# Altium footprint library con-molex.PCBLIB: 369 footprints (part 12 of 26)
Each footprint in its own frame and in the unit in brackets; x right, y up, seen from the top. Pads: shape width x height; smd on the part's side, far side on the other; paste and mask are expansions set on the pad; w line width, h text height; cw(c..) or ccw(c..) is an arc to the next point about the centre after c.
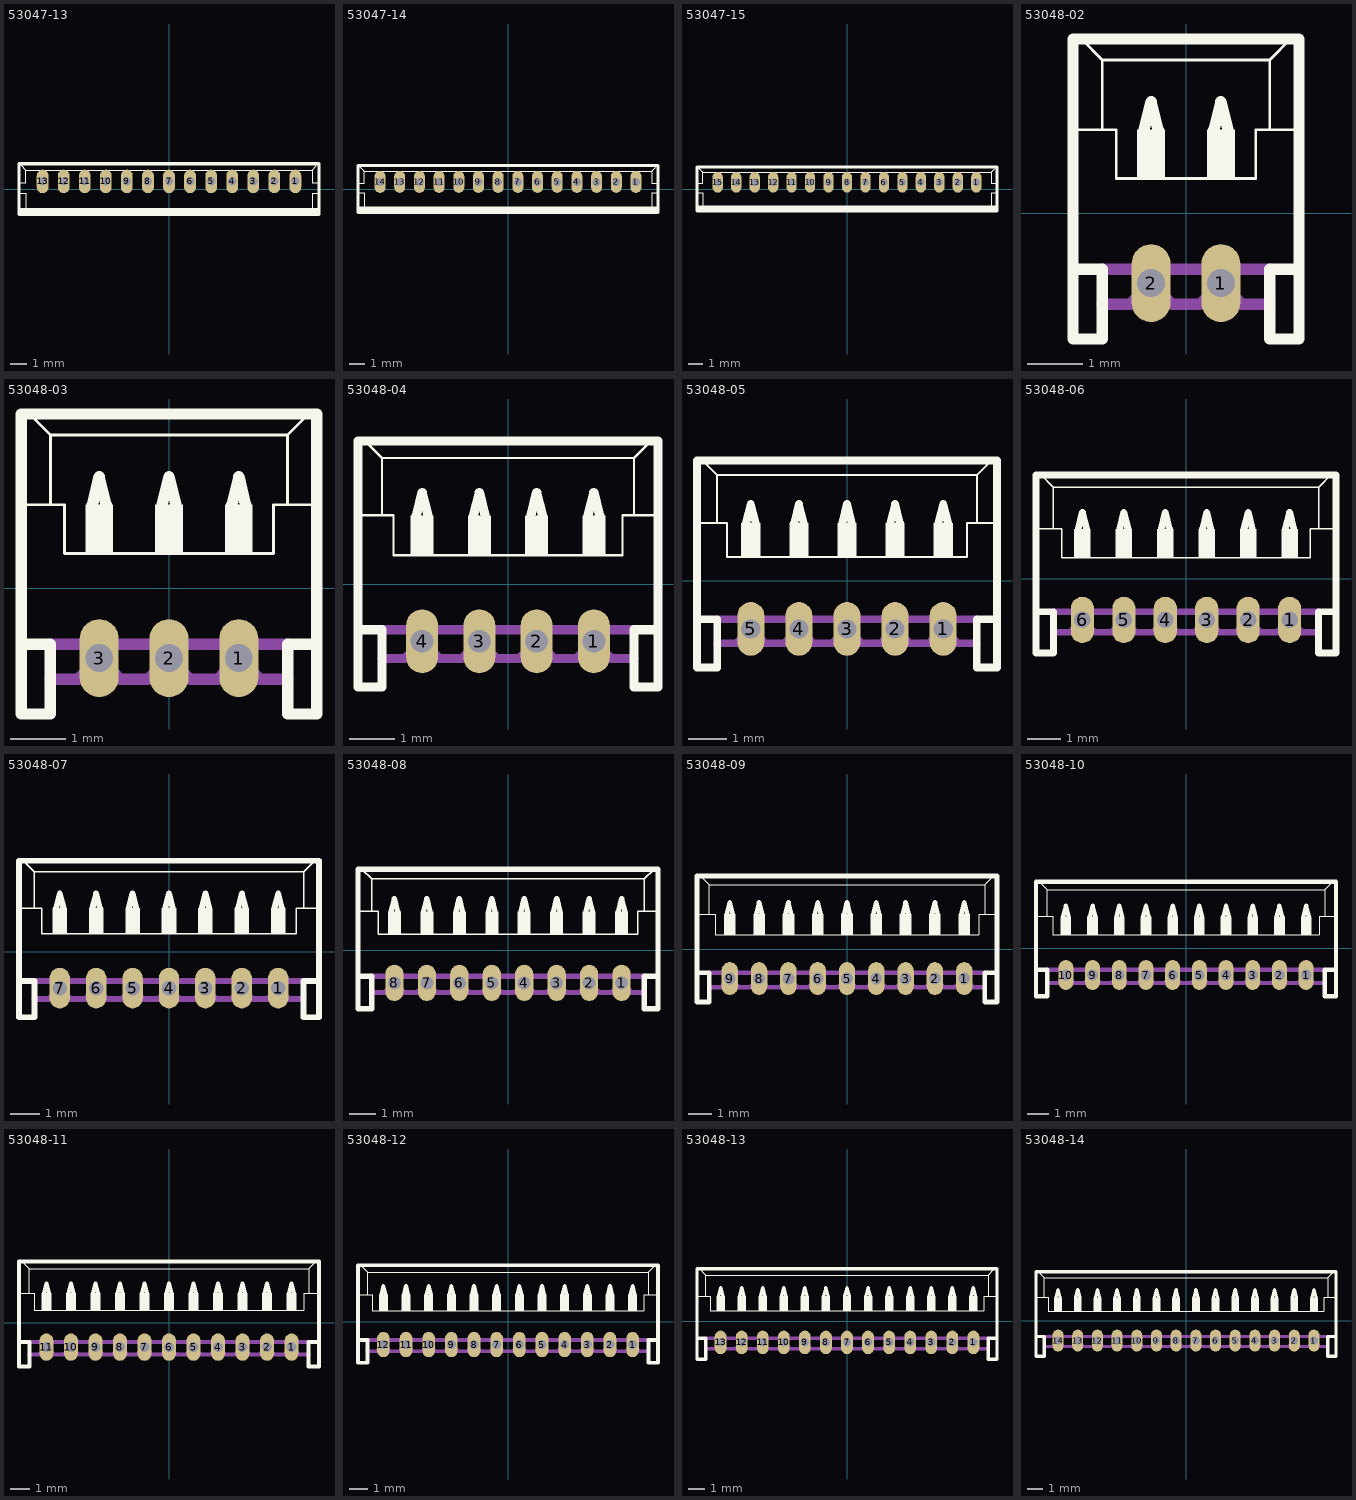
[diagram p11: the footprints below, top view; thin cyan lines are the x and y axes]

## 53047-13 [mil]
pads (13):
  oval 27.5x55 hole 19.69: 1(295.28,17.72) 2(246.06,17.72) 3(196.85,17.72) 4(147.64,17.72) 5(98.43,17.72) 6(49.21,17.72) 7(0,17.72) 8(-49.21,17.72) 9(-98.43,17.72) 10(-147.64,17.72) 11(-196.85,17.72) 12(-246.06,17.72) 13(-295.28,17.72)
Top Overlay:
  rectangle: -349.41,-59.06 349.41,-44.29
  lines w2: -349.41,-9.84 -334.65,-9.84 -334.65,-49.21 ; -349.41,14.76 -334.65,14.76 -334.65,44.29 ; -344.49,54.13 -334.65,44.29 ; 334.65,-49.21 334.65,-9.84 349.41,-9.84 ; 344.49,54.13 334.65,44.29 ; 349.41,14.76 334.65,14.76 334.65,44.29 ; -334.65,44.29 334.65,44.29
  lines w8: -350.39,-59.06 350.39,-59.06 350.39,59.06 -350.39,59.06 -350.39,-59.06

## 53047-14 [mil]
pads (14):
  oval 27.5x55 hole 19.69: 1(319.88,17.72) 2(270.67,17.72) 3(221.46,17.72) 4(172.24,17.72) 5(123.03,17.72) 6(73.82,17.72) 7(24.61,17.72) 8(-24.61,17.72) 9(-73.82,17.72) 10(-123.03,17.72) 11(-172.24,17.72) 12(-221.46,17.72) 13(-270.67,17.72) 14(-319.88,17.72)
Top Overlay:
  rectangle: -374.02,-59.06 374.02,-44.29
  lines w2: -374.02,-9.84 -359.25,-9.84 -359.25,-49.21 ; -374.02,14.76 -359.25,14.76 -359.25,44.29 ; -369.09,54.13 -359.25,44.29 ; 359.25,-49.21 359.25,-9.84 374.02,-9.84 ; 369.09,54.13 359.25,44.29 ; 374.02,14.76 359.25,14.76 359.25,44.29 ; -359.25,44.29 359.25,44.29
  lines w8: -375,-59.06 375,-59.06 375,59.06 -375,59.06 -375,-59.06

## 53047-15 [mil]
pads (15):
  oval 27.5x55 hole 19.69: 1(344.49,17.72) 2(295.28,17.72) 3(246.06,17.72) 4(196.85,17.72) 5(147.64,17.72) 6(98.43,17.72) 7(49.21,17.72) 8(0,17.72) 9(-49.21,17.72) 10(-98.43,17.72) 11(-147.64,17.72) 12(-196.85,17.72) 13(-246.06,17.72) 14(-295.28,17.72) 15(-344.49,17.72)
Top Overlay:
  rectangle: -398.62,-59.06 398.62,-44.29
  lines w2: -398.62,-9.84 -383.86,-9.84 -383.86,-49.21 ; -398.62,14.76 -383.86,14.76 -383.86,44.29 ; -393.7,54.13 -383.86,44.29 ; 383.86,-49.21 383.86,-9.84 398.62,-9.84 ; 393.7,54.13 383.86,44.29 ; 398.62,14.76 383.86,14.76 383.86,44.29 ; -383.86,44.29 383.86,44.29
  lines w8: -399.61,-59.06 399.61,-59.06 399.61,59.06 -399.61,59.06 -399.61,-59.06

## 53048-02 [mil]
pads (2):
  oval 27.5x55 hole 19.69: 1(24.61,-49.21) 2(-24.61,-49.21)
Top Overlay:
  rectangle: -34.45,24.61 -14.76,59.06
  rectangle: 14.76,24.61 34.45,59.06
  lines w2: -78.74,59.06 -59.06,59.06 ; -73.82,123.03 -59.06,108.27 ; 73.82,123.03 59.06,108.27 ; 78.74,59.06 59.06,59.06 ; -59.06,59.06 -49.21,59.06 -49.21,24.61 49.21,24.61 49.21,59.06 59.06,59.06 ; -59.06,59.06 -59.06,108.27 ; -59.06,108.27 59.06,108.27 ; 59.06,59.06 59.06,108.27
  lines w8: -78.74,-39.37 -59.06,-39.37 -59.06,-88.58 -79.72,-88.58 -79.72,123.03 -73.82,123.03 73.82,123.03 79.72,123.03 79.72,-88.58 59.06,-88.58 59.06,-39.37 78.74,-39.37 ; -29.53,59.06 -24.61,78.74 -19.69,59.06 ; 19.69,59.06 24.61,78.74 29.53,59.06
Mechanical 16:
  rectangle: -34.45,-59.06 -14.76,-39.37
  rectangle: 14.76,-59.06 34.45,-39.37
  lines w8: -59.06,-63.98 -39.37,-63.98 -34.45,-59.06 ; -59.06,-39.37 59.06,-39.37 ; -14.76,-59.06 -9.84,-63.98 9.84,-63.98 14.76,-59.06 ; 34.45,-59.06 39.37,-63.98 59.06,-63.98

## 53048-03 [mil]
pads (3):
  oval 27.5x55 hole 19.69: 1(49.21,-49.21) 2(0,-49.21) 3(-49.21,-49.21)
Top Overlay:
  rectangle: -59.06,24.61 -39.37,59.06
  rectangle: -9.84,24.61 9.84,59.06
  rectangle: 39.37,24.61 59.06,59.06
  lines w2: -103.35,59.06 -83.66,59.06 ; -98.43,123.03 -83.66,108.27 ; 98.43,123.03 83.66,108.27 ; 103.35,59.06 83.66,59.06 ; -83.66,59.06 -73.82,59.06 -73.82,24.61 73.82,24.61 73.82,59.06 83.66,59.06 ; -83.66,59.06 -83.66,108.27 ; -83.66,108.27 83.66,108.27 ; 83.66,59.06 83.66,108.27
  lines w8: -103.35,-39.37 -83.66,-39.37 -83.66,-88.58 -104.33,-88.58 -104.33,123.03 -98.43,123.03 98.43,123.03 104.33,123.03 104.33,-88.58 83.66,-88.58 83.66,-39.37 103.35,-39.37 ; -54.13,59.06 -49.21,78.74 -44.29,59.06 ; -4.92,59.06 0,78.74 4.92,59.06 ; 44.29,59.06 49.21,78.74 54.13,59.06
Mechanical 16:
  rectangle: -59.06,-59.06 -39.37,-39.37
  rectangle: -9.84,-59.06 9.84,-39.37
  rectangle: 39.37,-59.06 59.06,-39.37
  lines w8: -83.66,-63.98 -63.98,-63.98 -59.06,-59.06 ; -83.66,-39.37 83.66,-39.37 ; -39.37,-59.06 -34.45,-63.98 -14.76,-63.98 -9.84,-59.06 ; 9.84,-59.06 14.76,-63.98 34.45,-63.98 39.37,-59.06 ; 59.06,-59.06 63.98,-63.98 83.66,-63.98

## 53048-04 [mil]
pads (4):
  oval 27.5x55 hole 19.69: 1(73.82,-49.21) 2(24.61,-49.21) 3(-24.61,-49.21) 4(-73.82,-49.21)
Top Overlay:
  rectangle: -83.66,24.61 -63.98,59.06
  rectangle: -34.45,24.61 -14.76,59.06
  rectangle: 14.76,24.61 34.45,59.06
  rectangle: 63.98,24.61 83.66,59.06
  lines w2: -127.95,59.06 -108.27,59.06 ; -123.03,123.03 -108.27,108.27 ; 123.03,123.03 108.27,108.27 ; 127.95,59.06 108.27,59.06 ; -108.27,59.06 -98.43,59.06 -98.43,24.61 98.43,24.61 98.43,59.06 108.27,59.06 ; -108.27,59.06 -108.27,108.27 ; -108.27,108.27 108.27,108.27 ; 108.27,59.06 108.27,108.27
  lines w8: -127.95,-39.37 -108.27,-39.37 -108.27,-88.58 -128.94,-88.58 -128.94,123.03 -123.03,123.03 123.03,123.03 128.94,123.03 128.94,-88.58 108.27,-88.58 108.27,-39.37 127.95,-39.37 ; -78.74,59.06 -73.82,78.74 -68.9,59.06 ; -29.53,59.06 -24.61,78.74 -19.69,59.06 ; 19.69,59.06 24.61,78.74 29.53,59.06 ; 68.9,59.06 73.82,78.74 78.74,59.06
Mechanical 16:
  rectangle: -83.66,-59.06 -63.98,-39.37
  rectangle: -34.45,-59.06 -14.76,-39.37
  rectangle: 14.76,-59.06 34.45,-39.37
  rectangle: 63.98,-59.06 83.66,-39.37
  lines w8: -108.27,-63.98 -88.58,-63.98 -83.66,-59.06 ; -108.27,-39.37 108.27,-39.37 ; -63.98,-59.06 -59.06,-63.98 -39.37,-63.98 -34.45,-59.06 ; -14.76,-59.06 -9.84,-63.98 9.84,-63.98 14.76,-59.06 ; 34.45,-59.06 39.37,-63.98 59.06,-63.98 63.98,-59.06 ; 83.66,-59.06 88.58,-63.98 108.27,-63.98

## 53048-05 [mil]
pads (5):
  oval 27.5x55 hole 19.69: 1(98.43,-49.21) 2(49.21,-49.21) 3(0,-49.21) 4(-49.21,-49.21) 5(-98.43,-49.21)
Top Overlay:
  rectangle: -108.27,24.61 -88.58,59.06
  rectangle: -59.06,24.61 -39.37,59.06
  rectangle: -9.84,24.61 9.84,59.06
  rectangle: 39.37,24.61 59.06,59.06
  rectangle: 88.58,24.61 108.27,59.06
  lines w2: -152.56,59.06 -132.87,59.06 ; -147.64,123.03 -132.87,108.27 ; 147.64,123.03 132.87,108.27 ; 152.56,59.06 132.87,59.06 ; -132.87,59.06 -123.03,59.06 -123.03,24.61 123.03,24.61 123.03,59.06 132.87,59.06 ; -132.87,59.06 -132.87,108.27 ; -132.87,108.27 132.87,108.27 ; 132.87,59.06 132.87,108.27
  lines w8: -152.56,-39.37 -132.87,-39.37 -132.87,-88.58 -153.54,-88.58 -153.54,123.03 -147.64,123.03 147.64,123.03 153.54,123.03 153.54,-88.58 132.87,-88.58 132.87,-39.37 152.56,-39.37 ; -103.35,59.06 -98.43,78.74 -93.5,59.06 ; -54.13,59.06 -49.21,78.74 -44.29,59.06 ; -4.92,59.06 0,78.74 4.92,59.06 ; 44.29,59.06 49.21,78.74 54.13,59.06 ; 93.5,59.06 98.43,78.74 103.35,59.06
Mechanical 16:
  rectangle: -108.27,-59.06 -88.58,-39.37
  rectangle: -59.06,-59.06 -39.37,-39.37
  rectangle: -9.84,-59.06 9.84,-39.37
  rectangle: 39.37,-59.06 59.06,-39.37
  rectangle: 88.58,-59.06 108.27,-39.37
  lines w8: -132.87,-63.98 -113.19,-63.98 -108.27,-59.06 ; -132.87,-39.37 132.87,-39.37 ; -88.58,-59.06 -83.66,-63.98 -63.98,-63.98 -59.06,-59.06 ; -39.37,-59.06 -34.45,-63.98 -14.76,-63.98 -9.84,-59.06 ; 9.84,-59.06 14.76,-63.98 34.45,-63.98 39.37,-59.06 ; 59.06,-59.06 63.98,-63.98 83.66,-63.98 88.58,-59.06 ; 108.27,-59.06 113.19,-63.98 132.87,-63.98

## 53048-06 [mil]
pads (6):
  oval 27.5x55 hole 19.69: 1(123.03,-49.21) 2(73.82,-49.21) 3(24.61,-49.21) 4(-24.61,-49.21) 5(-73.82,-49.21) 6(-123.03,-49.21)
Top Overlay:
  rectangle: -132.87,24.61 -113.19,59.06
  rectangle: -83.66,24.61 -63.98,59.06
  rectangle: -34.45,24.61 -14.76,59.06
  rectangle: 14.76,24.61 34.45,59.06
  rectangle: 63.98,24.61 83.66,59.06
  rectangle: 113.19,24.61 132.87,59.06
  lines w2: -177.17,59.06 -157.48,59.06 ; -172.24,123.03 -157.48,108.27 ; 172.24,123.03 157.48,108.27 ; 177.17,59.06 157.48,59.06 ; -157.48,59.06 -147.64,59.06 -147.64,24.61 147.64,24.61 147.64,59.06 157.48,59.06 ; -157.48,59.06 -157.48,108.27 ; -157.48,108.27 157.48,108.27 ; 157.48,59.06 157.48,108.27
  lines w8: -177.17,-39.37 -157.48,-39.37 -157.48,-88.58 -178.15,-88.58 -178.15,123.03 -172.24,123.03 172.24,123.03 178.15,123.03 178.15,-88.58 157.48,-88.58 157.48,-39.37 177.17,-39.37 ; -127.95,59.06 -123.03,78.74 -118.11,59.06 ; -78.74,59.06 -73.82,78.74 -68.9,59.06 ; -29.53,59.06 -24.61,78.74 -19.69,59.06 ; 19.69,59.06 24.61,78.74 29.53,59.06 ; 68.9,59.06 73.82,78.74 78.74,59.06 ; 118.11,59.06 123.03,78.74 127.95,59.06
Mechanical 16:
  rectangle: -132.87,-59.06 -113.19,-39.37
  rectangle: -83.66,-59.06 -63.98,-39.37
  rectangle: -34.45,-59.06 -14.76,-39.37
  rectangle: 14.76,-59.06 34.45,-39.37
  rectangle: 63.98,-59.06 83.66,-39.37
  rectangle: 113.19,-59.06 132.87,-39.37
  lines w8: -157.48,-63.98 -137.8,-63.98 -132.87,-59.06 ; -157.48,-39.37 157.48,-39.37 ; -113.19,-59.06 -108.27,-63.98 -88.58,-63.98 -83.66,-59.06 ; -63.98,-59.06 -59.06,-63.98 -39.37,-63.98 -34.45,-59.06 ; -14.76,-59.06 -9.84,-63.98 9.84,-63.98 14.76,-59.06 ; 34.45,-59.06 39.37,-63.98 59.06,-63.98 63.98,-59.06 ; 83.66,-59.06 88.58,-63.98 108.27,-63.98 113.19,-59.06 ; 132.87,-59.06 137.8,-63.98 157.48,-63.98

## 53048-07 [mil]
pads (7):
  oval 27.5x55 hole 19.69: 1(147.64,-49.21) 2(98.43,-49.21) 3(49.21,-49.21) 4(0,-49.21) 5(-49.21,-49.21) 6(-98.43,-49.21) 7(-147.64,-49.21)
Top Overlay:
  rectangle: -157.48,24.61 -137.8,59.06
  rectangle: -108.27,24.61 -88.58,59.06
  rectangle: -59.06,24.61 -39.37,59.06
  rectangle: -9.84,24.61 9.84,59.06
  rectangle: 39.37,24.61 59.06,59.06
  rectangle: 88.58,24.61 108.27,59.06
  rectangle: 137.8,24.61 157.48,59.06
  lines w2: -201.77,59.06 -182.09,59.06 ; -196.85,123.03 -182.09,108.27 ; 196.85,123.03 182.09,108.27 ; 201.77,59.06 182.09,59.06 ; -182.09,59.06 -172.24,59.06 -172.24,24.61 172.24,24.61 172.24,59.06 182.09,59.06 ; -182.09,59.06 -182.09,108.27 ; -182.09,108.27 182.09,108.27 ; 182.09,59.06 182.09,108.27
  lines w8: -201.77,-39.37 -182.09,-39.37 -182.09,-88.58 -202.76,-88.58 -202.76,123.03 -196.85,123.03 196.85,123.03 202.76,123.03 202.76,-88.58 182.09,-88.58 182.09,-39.37 201.77,-39.37 ; -152.56,59.06 -147.64,78.74 -142.72,59.06 ; -103.35,59.06 -98.43,78.74 -93.5,59.06 ; -54.13,59.06 -49.21,78.74 -44.29,59.06 ; -4.92,59.06 0,78.74 4.92,59.06 ; 44.29,59.06 49.21,78.74 54.13,59.06 ; 93.5,59.06 98.43,78.74 103.35,59.06 ; 142.72,59.06 147.64,78.74 152.56,59.06
Mechanical 16:
  rectangle: -157.48,-59.06 -137.8,-39.37
  rectangle: -108.27,-59.06 -88.58,-39.37
  rectangle: -59.06,-59.06 -39.37,-39.37
  rectangle: -9.84,-59.06 9.84,-39.37
  rectangle: 39.37,-59.06 59.06,-39.37
  rectangle: 88.58,-59.06 108.27,-39.37
  rectangle: 137.8,-59.06 157.48,-39.37
  lines w8: -182.09,-63.98 -162.4,-63.98 -157.48,-59.06 ; -182.09,-39.37 182.09,-39.37 ; -137.8,-59.06 -132.87,-63.98 -113.19,-63.98 -108.27,-59.06 ; -88.58,-59.06 -83.66,-63.98 -63.98,-63.98 -59.06,-59.06 ; -39.37,-59.06 -34.45,-63.98 -14.76,-63.98 -9.84,-59.06 ; 9.84,-59.06 14.76,-63.98 34.45,-63.98 39.37,-59.06 ; 59.06,-59.06 63.98,-63.98 83.66,-63.98 88.58,-59.06 ; 108.27,-59.06 113.19,-63.98 132.87,-63.98 137.8,-59.06 ; 157.48,-59.06 162.4,-63.98 182.09,-63.98

## 53048-08 [mil]
pads (8):
  oval 27.5x55 hole 19.69: 1(172.24,-49.21) 2(123.03,-49.21) 3(73.82,-49.21) 4(24.61,-49.21) 5(-24.61,-49.21) 6(-73.82,-49.21) 7(-123.03,-49.21) 8(-172.24,-49.21)
Top Overlay:
  rectangle: -182.09,24.61 -162.4,59.06
  rectangle: -132.87,24.61 -113.19,59.06
  rectangle: -83.66,24.61 -63.98,59.06
  rectangle: -34.45,24.61 -14.76,59.06
  rectangle: 14.76,24.61 34.45,59.06
  rectangle: 63.98,24.61 83.66,59.06
  rectangle: 113.19,24.61 132.87,59.06
  rectangle: 162.4,24.61 182.09,59.06
  lines w2: -226.38,59.06 -206.69,59.06 ; -221.46,123.03 -206.69,108.27 ; 221.46,123.03 206.69,108.27 ; 226.38,59.06 206.69,59.06 ; -206.69,59.06 -196.85,59.06 -196.85,24.61 196.85,24.61 196.85,59.06 206.69,59.06 ; -206.69,59.06 -206.69,108.27 ; -206.69,108.27 206.69,108.27 ; 206.69,59.06 206.69,108.27
  lines w8: -226.38,-39.37 -206.69,-39.37 -206.69,-88.58 -227.36,-88.58 -227.36,123.03 -221.46,123.03 221.46,123.03 227.36,123.03 227.36,-88.58 206.69,-88.58 206.69,-39.37 226.38,-39.37 ; -177.17,59.06 -172.24,78.74 -167.32,59.06 ; -127.95,59.06 -123.03,78.74 -118.11,59.06 ; -78.74,59.06 -73.82,78.74 -68.9,59.06 ; -29.53,59.06 -24.61,78.74 -19.69,59.06 ; 19.69,59.06 24.61,78.74 29.53,59.06 ; 68.9,59.06 73.82,78.74 78.74,59.06 ; 118.11,59.06 123.03,78.74 127.95,59.06 ; 167.32,59.06 172.24,78.74 177.17,59.06
Mechanical 16:
  rectangle: -182.09,-59.06 -162.4,-39.37
  rectangle: -132.87,-59.06 -113.19,-39.37
  rectangle: -83.66,-59.06 -63.98,-39.37
  rectangle: -34.45,-59.06 -14.76,-39.37
  rectangle: 14.76,-59.06 34.45,-39.37
  rectangle: 63.98,-59.06 83.66,-39.37
  rectangle: 113.19,-59.06 132.87,-39.37
  rectangle: 162.4,-59.06 182.09,-39.37
  lines w8: -206.69,-63.98 -187.01,-63.98 -182.09,-59.06 ; -206.69,-39.37 206.69,-39.37 ; -162.4,-59.06 -157.48,-63.98 -137.8,-63.98 -132.87,-59.06 ; -113.19,-59.06 -108.27,-63.98 -88.58,-63.98 -83.66,-59.06 ; -63.98,-59.06 -59.06,-63.98 -39.37,-63.98 -34.45,-59.06 ; -14.76,-59.06 -9.84,-63.98 9.84,-63.98 14.76,-59.06 ; 34.45,-59.06 39.37,-63.98 59.06,-63.98 63.98,-59.06 ; 83.66,-59.06 88.58,-63.98 108.27,-63.98 113.19,-59.06 ; 132.87,-59.06 137.8,-63.98 157.48,-63.98 162.4,-59.06 ; 182.09,-59.06 187.01,-63.98 206.69,-63.98

## 53048-09 [mil]
pads (9):
  oval 27.5x55 hole 19.69: 1(196.85,-49.21) 2(147.64,-49.21) 3(98.43,-49.21) 4(49.21,-49.21) 5(0,-49.21) 6(-49.21,-49.21) 7(-98.43,-49.21) 8(-147.64,-49.21) 9(-196.85,-49.21)
Top Overlay:
  rectangle: -206.69,24.61 -187.01,59.06
  rectangle: -157.48,24.61 -137.8,59.06
  rectangle: -108.27,24.61 -88.58,59.06
  rectangle: -59.06,24.61 -39.37,59.06
  rectangle: -9.84,24.61 9.84,59.06
  rectangle: 39.37,24.61 59.06,59.06
  rectangle: 88.58,24.61 108.27,59.06
  rectangle: 137.8,24.61 157.48,59.06
  rectangle: 187.01,24.61 206.69,59.06
  lines w2: -250.98,59.06 -231.3,59.06 ; -246.06,123.03 -231.3,108.27 ; 246.06,123.03 231.3,108.27 ; 250.98,59.06 231.3,59.06 ; -231.3,59.06 -221.46,59.06 -221.46,24.61 221.46,24.61 221.46,59.06 231.3,59.06 ; -231.3,59.06 -231.3,108.27 ; -231.3,108.27 231.3,108.27 ; 231.3,59.06 231.3,108.27
  lines w8: -250.98,-39.37 -231.3,-39.37 -231.3,-88.58 -251.97,-88.58 -251.97,123.03 -246.06,123.03 246.06,123.03 251.97,123.03 251.97,-88.58 231.3,-88.58 231.3,-39.37 250.98,-39.37 ; -201.77,59.06 -196.85,78.74 -191.93,59.06 ; -152.56,59.06 -147.64,78.74 -142.72,59.06 ; -103.35,59.06 -98.43,78.74 -93.5,59.06 ; -54.13,59.06 -49.21,78.74 -44.29,59.06 ; -4.92,59.06 0,78.74 4.92,59.06 ; 44.29,59.06 49.21,78.74 54.13,59.06 ; 93.5,59.06 98.43,78.74 103.35,59.06 ; 142.72,59.06 147.64,78.74 152.56,59.06 ; 191.93,59.06 196.85,78.74 201.77,59.06
Mechanical 16:
  rectangle: -206.69,-59.06 -187.01,-39.37
  rectangle: -157.48,-59.06 -137.8,-39.37
  rectangle: -108.27,-59.06 -88.58,-39.37
  rectangle: -59.06,-59.06 -39.37,-39.37
  rectangle: -9.84,-59.06 9.84,-39.37
  rectangle: 39.37,-59.06 59.06,-39.37
  rectangle: 88.58,-59.06 108.27,-39.37
  rectangle: 137.8,-59.06 157.48,-39.37
  rectangle: 187.01,-59.06 206.69,-39.37
  lines w8: -231.3,-63.98 -211.61,-63.98 -206.69,-59.06 ; -231.3,-39.37 231.3,-39.37 ; -187.01,-59.06 -182.09,-63.98 -162.4,-63.98 -157.48,-59.06 ; -137.8,-59.06 -132.87,-63.98 -113.19,-63.98 -108.27,-59.06 ; -88.58,-59.06 -83.66,-63.98 -63.98,-63.98 -59.06,-59.06 ; -39.37,-59.06 -34.45,-63.98 -14.76,-63.98 -9.84,-59.06 ; 9.84,-59.06 14.76,-63.98 34.45,-63.98 39.37,-59.06 ; 59.06,-59.06 63.98,-63.98 83.66,-63.98 88.58,-59.06 ; 108.27,-59.06 113.19,-63.98 132.87,-63.98 137.8,-59.06 ; 157.48,-59.06 162.4,-63.98 182.09,-63.98 187.01,-59.06 ; 206.69,-59.06 211.61,-63.98 231.3,-63.98

## 53048-10 [mil]
pads (10):
  oval 27.5x55 hole 19.69: 1(221.46,-49.21) 2(172.24,-49.21) 3(123.03,-49.21) 4(73.82,-49.21) 5(24.61,-49.21) 6(-24.61,-49.21) 7(-73.82,-49.21) 8(-123.03,-49.21) 9(-172.24,-49.21) 10(-221.46,-49.21)
Top Overlay:
  rectangle: -231.3,24.61 -211.61,59.06
  rectangle: -182.09,24.61 -162.4,59.06
  rectangle: -132.87,24.61 -113.19,59.06
  rectangle: -83.66,24.61 -63.98,59.06
  rectangle: -34.45,24.61 -14.76,59.06
  rectangle: 14.76,24.61 34.45,59.06
  rectangle: 63.98,24.61 83.66,59.06
  rectangle: 113.19,24.61 132.87,59.06
  rectangle: 162.4,24.61 182.09,59.06
  rectangle: 211.61,24.61 231.3,59.06
  lines w2: -275.59,59.06 -255.91,59.06 ; -270.67,123.03 -255.91,108.27 ; 270.67,123.03 255.91,108.27 ; 275.59,59.06 255.91,59.06 ; -255.91,59.06 -246.06,59.06 -246.06,24.61 246.06,24.61 246.06,59.06 255.91,59.06 ; -255.91,59.06 -255.91,108.27 ; -255.91,108.27 255.91,108.27 ; 255.91,59.06 255.91,108.27
  lines w8: -275.59,-39.37 -255.91,-39.37 -255.91,-88.58 -276.57,-88.58 -276.57,123.03 -270.67,123.03 270.67,123.03 276.57,123.03 276.57,-88.58 255.91,-88.58 255.91,-39.37 275.59,-39.37 ; -226.38,59.06 -221.46,78.74 -216.54,59.06 ; -177.17,59.06 -172.24,78.74 -167.32,59.06 ; -127.95,59.06 -123.03,78.74 -118.11,59.06 ; -78.74,59.06 -73.82,78.74 -68.9,59.06 ; -29.53,59.06 -24.61,78.74 -19.69,59.06 ; 19.69,59.06 24.61,78.74 29.53,59.06 ; 68.9,59.06 73.82,78.74 78.74,59.06 ; 118.11,59.06 123.03,78.74 127.95,59.06 ; 167.32,59.06 172.24,78.74 177.17,59.06 ; 216.54,59.06 221.46,78.74 226.38,59.06
Mechanical 16:
  rectangle: -231.3,-59.06 -211.61,-39.37
  rectangle: -182.09,-59.06 -162.4,-39.37
  rectangle: -132.87,-59.06 -113.19,-39.37
  rectangle: -83.66,-59.06 -63.98,-39.37
  rectangle: -34.45,-59.06 -14.76,-39.37
  rectangle: 14.76,-59.06 34.45,-39.37
  rectangle: 63.98,-59.06 83.66,-39.37
  rectangle: 113.19,-59.06 132.87,-39.37
  rectangle: 162.4,-59.06 182.09,-39.37
  rectangle: 211.61,-59.06 231.3,-39.37
  lines w8: -255.91,-63.98 -236.22,-63.98 -231.3,-59.06 ; -255.91,-39.37 255.91,-39.37 ; -211.61,-59.06 -206.69,-63.98 -187.01,-63.98 -182.09,-59.06 ; -162.4,-59.06 -157.48,-63.98 -137.8,-63.98 -132.87,-59.06 ; -113.19,-59.06 -108.27,-63.98 -88.58,-63.98 -83.66,-59.06 ; -63.98,-59.06 -59.06,-63.98 -39.37,-63.98 -34.45,-59.06 ; -14.76,-59.06 -9.84,-63.98 9.84,-63.98 14.76,-59.06 ; 34.45,-59.06 39.37,-63.98 59.06,-63.98 63.98,-59.06 ; 83.66,-59.06 88.58,-63.98 108.27,-63.98 113.19,-59.06 ; 132.87,-59.06 137.8,-63.98 157.48,-63.98 162.4,-59.06 ; 182.09,-59.06 187.01,-63.98 206.69,-63.98 211.61,-59.06 ; 231.3,-59.06 236.22,-63.98 255.91,-63.98

## 53048-11 [mil]
pads (11):
  oval 27.5x55 hole 19.69: 1(246.06,-49.21) 2(196.85,-49.21) 3(147.64,-49.21) 4(98.43,-49.21) 5(49.21,-49.21) 6(0,-49.21) 7(-49.21,-49.21) 8(-98.43,-49.21) 9(-147.64,-49.21) 10(-196.85,-49.21) 11(-246.06,-49.21)
Top Overlay:
  rectangle: -255.91,24.61 -236.22,59.06
  rectangle: -206.69,24.61 -187.01,59.06
  rectangle: -157.48,24.61 -137.8,59.06
  rectangle: -108.27,24.61 -88.58,59.06
  rectangle: -59.06,24.61 -39.37,59.06
  rectangle: -9.84,24.61 9.84,59.06
  rectangle: 39.37,24.61 59.06,59.06
  rectangle: 88.58,24.61 108.27,59.06
  rectangle: 137.8,24.61 157.48,59.06
  rectangle: 187.01,24.61 206.69,59.06
  rectangle: 236.22,24.61 255.91,59.06
  lines w2: -300.2,59.06 -280.51,59.06 ; -295.28,123.03 -280.51,108.27 ; 295.28,123.03 280.51,108.27 ; 300.2,59.06 280.51,59.06 ; -280.51,59.06 -270.67,59.06 -270.67,24.61 270.67,24.61 270.67,59.06 280.51,59.06 ; -280.51,59.06 -280.51,108.27 ; -280.51,108.27 280.51,108.27 ; 280.51,59.06 280.51,108.27
  lines w8: -300.2,-39.37 -280.51,-39.37 -280.51,-88.58 -301.18,-88.58 -301.18,123.03 -295.28,123.03 295.28,123.03 301.18,123.03 301.18,-88.58 280.51,-88.58 280.51,-39.37 300.2,-39.37 ; -250.98,59.06 -246.06,78.74 -241.14,59.06 ; -201.77,59.06 -196.85,78.74 -191.93,59.06 ; -152.56,59.06 -147.64,78.74 -142.72,59.06 ; -103.35,59.06 -98.43,78.74 -93.5,59.06 ; -54.13,59.06 -49.21,78.74 -44.29,59.06 ; -4.92,59.06 0,78.74 4.92,59.06 ; 44.29,59.06 49.21,78.74 54.13,59.06 ; 93.5,59.06 98.43,78.74 103.35,59.06 ; 142.72,59.06 147.64,78.74 152.56,59.06 ; 191.93,59.06 196.85,78.74 201.77,59.06 ; 241.14,59.06 246.06,78.74 250.98,59.06
Mechanical 16:
  rectangle: -255.91,-59.06 -236.22,-39.37
  rectangle: -206.69,-59.06 -187.01,-39.37
  rectangle: -157.48,-59.06 -137.8,-39.37
  rectangle: -108.27,-59.06 -88.58,-39.37
  rectangle: -59.06,-59.06 -39.37,-39.37
  rectangle: -9.84,-59.06 9.84,-39.37
  rectangle: 39.37,-59.06 59.06,-39.37
  rectangle: 88.58,-59.06 108.27,-39.37
  rectangle: 137.8,-59.06 157.48,-39.37
  rectangle: 187.01,-59.06 206.69,-39.37
  rectangle: 236.22,-59.06 255.91,-39.37
  lines w8: -280.51,-63.98 -260.83,-63.98 -255.91,-59.06 ; -280.51,-39.37 280.51,-39.37 ; -236.22,-59.06 -231.3,-63.98 -211.61,-63.98 -206.69,-59.06 ; -187.01,-59.06 -182.09,-63.98 -162.4,-63.98 -157.48,-59.06 ; -137.8,-59.06 -132.87,-63.98 -113.19,-63.98 -108.27,-59.06 ; -88.58,-59.06 -83.66,-63.98 -63.98,-63.98 -59.06,-59.06 ; -39.37,-59.06 -34.45,-63.98 -14.76,-63.98 -9.84,-59.06 ; 9.84,-59.06 14.76,-63.98 34.45,-63.98 39.37,-59.06 ; 59.06,-59.06 63.98,-63.98 83.66,-63.98 88.58,-59.06 ; 108.27,-59.06 113.19,-63.98 132.87,-63.98 137.8,-59.06 ; 157.48,-59.06 162.4,-63.98 182.09,-63.98 187.01,-59.06 ; 206.69,-59.06 211.61,-63.98 231.3,-63.98 236.22,-59.06 ; 255.91,-59.06 260.83,-63.98 280.51,-63.98

## 53048-12 [mil]
pads (12):
  oval 27.5x55 hole 19.69: 1(270.67,-49.21) 2(221.46,-49.21) 3(172.24,-49.21) 4(123.03,-49.21) 5(73.82,-49.21) 6(24.61,-49.21) 7(-24.61,-49.21) 8(-73.82,-49.21) 9(-123.03,-49.21) 10(-172.24,-49.21) 11(-221.46,-49.21) 12(-270.67,-49.21)
Top Overlay:
  rectangle: -280.51,24.61 -260.83,59.06
  rectangle: -231.3,24.61 -211.61,59.06
  rectangle: -182.09,24.61 -162.4,59.06
  rectangle: -132.87,24.61 -113.19,59.06
  rectangle: -83.66,24.61 -63.98,59.06
  rectangle: -34.45,24.61 -14.76,59.06
  rectangle: 14.76,24.61 34.45,59.06
  rectangle: 63.98,24.61 83.66,59.06
  rectangle: 113.19,24.61 132.87,59.06
  rectangle: 162.4,24.61 182.09,59.06
  rectangle: 211.61,24.61 231.3,59.06
  rectangle: 260.83,24.61 280.51,59.06
  lines w2: -324.8,59.06 -305.12,59.06 ; -319.88,123.03 -305.12,108.27 ; 319.88,123.03 305.12,108.27 ; 324.8,59.06 305.12,59.06 ; -305.12,59.06 -295.28,59.06 -295.28,24.61 295.28,24.61 295.28,59.06 305.12,59.06 ; -305.12,59.06 -305.12,108.27 ; -305.12,108.27 305.12,108.27 ; 305.12,59.06 305.12,108.27
  lines w8: -324.8,-39.37 -305.12,-39.37 -305.12,-88.58 -325.79,-88.58 -325.79,123.03 -319.88,123.03 319.88,123.03 325.79,123.03 325.79,-88.58 305.12,-88.58 305.12,-39.37 324.8,-39.37 ; -275.59,59.06 -270.67,78.74 -265.75,59.06 ; -226.38,59.06 -221.46,78.74 -216.54,59.06 ; -177.17,59.06 -172.24,78.74 -167.32,59.06 ; -127.95,59.06 -123.03,78.74 -118.11,59.06 ; -78.74,59.06 -73.82,78.74 -68.9,59.06 ; -29.53,59.06 -24.61,78.74 -19.69,59.06 ; 19.69,59.06 24.61,78.74 29.53,59.06 ; 68.9,59.06 73.82,78.74 78.74,59.06 ; 118.11,59.06 123.03,78.74 127.95,59.06 ; 167.32,59.06 172.24,78.74 177.17,59.06 ; 216.54,59.06 221.46,78.74 226.38,59.06 ; 265.75,59.06 270.67,78.74 275.59,59.06
Mechanical 16:
  rectangle: -280.51,-59.06 -260.83,-39.37
  rectangle: -231.3,-59.06 -211.61,-39.37
  rectangle: -182.09,-59.06 -162.4,-39.37
  rectangle: -132.87,-59.06 -113.19,-39.37
  rectangle: -83.66,-59.06 -63.98,-39.37
  rectangle: -34.45,-59.06 -14.76,-39.37
  rectangle: 14.76,-59.06 34.45,-39.37
  rectangle: 63.98,-59.06 83.66,-39.37
  rectangle: 113.19,-59.06 132.87,-39.37
  rectangle: 162.4,-59.06 182.09,-39.37
  rectangle: 211.61,-59.06 231.3,-39.37
  rectangle: 260.83,-59.06 280.51,-39.37
  lines w8: -305.12,-63.98 -285.43,-63.98 -280.51,-59.06 ; -305.12,-39.37 305.12,-39.37 ; -260.83,-59.06 -255.91,-63.98 -236.22,-63.98 -231.3,-59.06 ; -211.61,-59.06 -206.69,-63.98 -187.01,-63.98 -182.09,-59.06 ; -162.4,-59.06 -157.48,-63.98 -137.8,-63.98 -132.87,-59.06 ; -113.19,-59.06 -108.27,-63.98 -88.58,-63.98 -83.66,-59.06 ; -63.98,-59.06 -59.06,-63.98 -39.37,-63.98 -34.45,-59.06 ; -14.76,-59.06 -9.84,-63.98 9.84,-63.98 14.76,-59.06 ; 34.45,-59.06 39.37,-63.98 59.06,-63.98 63.98,-59.06 ; 83.66,-59.06 88.58,-63.98 108.27,-63.98 113.19,-59.06 ; 132.87,-59.06 137.8,-63.98 157.48,-63.98 162.4,-59.06 ; 182.09,-59.06 187.01,-63.98 206.69,-63.98 211.61,-59.06 ; 231.3,-59.06 236.22,-63.98 255.91,-63.98 260.83,-59.06 ; 280.51,-59.06 285.43,-63.98 305.12,-63.98

## 53048-13 [mil]
pads (13):
  oval 27.5x55 hole 19.69: 1(295.28,-49.21) 2(246.06,-49.21) 3(196.85,-49.21) 4(147.64,-49.21) 5(98.43,-49.21) 6(49.21,-49.21) 7(0,-49.21) 8(-49.21,-49.21) 9(-98.43,-49.21) 10(-147.64,-49.21) 11(-196.85,-49.21) 12(-246.06,-49.21) 13(-295.28,-49.21)
Top Overlay:
  rectangle: -305.12,24.61 -285.43,59.06
  rectangle: -255.91,24.61 -236.22,59.06
  rectangle: -206.69,24.61 -187.01,59.06
  rectangle: -157.48,24.61 -137.8,59.06
  rectangle: -108.27,24.61 -88.58,59.06
  rectangle: -59.06,24.61 -39.37,59.06
  rectangle: -9.84,24.61 9.84,59.06
  rectangle: 39.37,24.61 59.06,59.06
  rectangle: 88.58,24.61 108.27,59.06
  rectangle: 137.8,24.61 157.48,59.06
  rectangle: 187.01,24.61 206.69,59.06
  rectangle: 236.22,24.61 255.91,59.06
  rectangle: 285.43,24.61 305.12,59.06
  lines w2: -349.41,59.06 -329.72,59.06 ; -344.49,123.03 -329.72,108.27 ; 344.49,123.03 329.72,108.27 ; 349.41,59.06 329.72,59.06 ; -329.72,59.06 -319.88,59.06 -319.88,24.61 319.88,24.61 319.88,59.06 329.72,59.06 ; -329.72,59.06 -329.72,108.27 ; -329.72,108.27 329.72,108.27 ; 329.72,59.06 329.72,108.27
  lines w8: -349.41,-39.37 -329.72,-39.37 -329.72,-88.58 -350.39,-88.58 -350.39,123.03 -344.49,123.03 344.49,123.03 350.39,123.03 350.39,-88.58 329.72,-88.58 329.72,-39.37 349.41,-39.37 ; -300.2,59.06 -295.28,78.74 -290.35,59.06 ; -250.98,59.06 -246.06,78.74 -241.14,59.06 ; -201.77,59.06 -196.85,78.74 -191.93,59.06 ; -152.56,59.06 -147.64,78.74 -142.72,59.06 ; -103.35,59.06 -98.43,78.74 -93.5,59.06 ; -54.13,59.06 -49.21,78.74 -44.29,59.06 ; -4.92,59.06 0,78.74 4.92,59.06 ; 44.29,59.06 49.21,78.74 54.13,59.06 ; 93.5,59.06 98.43,78.74 103.35,59.06 ; 142.72,59.06 147.64,78.74 152.56,59.06 ; 191.93,59.06 196.85,78.74 201.77,59.06 ; 241.14,59.06 246.06,78.74 250.98,59.06 ; 290.35,59.06 295.28,78.74 300.2,59.06
Mechanical 16:
  rectangle: -305.12,-59.06 -285.43,-39.37
  rectangle: -255.91,-59.06 -236.22,-39.37
  rectangle: -206.69,-59.06 -187.01,-39.37
  rectangle: -157.48,-59.06 -137.8,-39.37
  rectangle: -108.27,-59.06 -88.58,-39.37
  rectangle: -59.06,-59.06 -39.37,-39.37
  rectangle: -9.84,-59.06 9.84,-39.37
  rectangle: 39.37,-59.06 59.06,-39.37
  rectangle: 88.58,-59.06 108.27,-39.37
  rectangle: 137.8,-59.06 157.48,-39.37
  rectangle: 187.01,-59.06 206.69,-39.37
  rectangle: 236.22,-59.06 255.91,-39.37
  rectangle: 285.43,-59.06 305.12,-39.37
  lines w8: -329.72,-63.98 -310.04,-63.98 -305.12,-59.06 ; -329.72,-39.37 329.72,-39.37 ; -285.43,-59.06 -280.51,-63.98 -260.83,-63.98 -255.91,-59.06 ; -236.22,-59.06 -231.3,-63.98 -211.61,-63.98 -206.69,-59.06 ; -187.01,-59.06 -182.09,-63.98 -162.4,-63.98 -157.48,-59.06 ; -137.8,-59.06 -132.87,-63.98 -113.19,-63.98 -108.27,-59.06 ; -88.58,-59.06 -83.66,-63.98 -63.98,-63.98 -59.06,-59.06 ; -39.37,-59.06 -34.45,-63.98 -14.76,-63.98 -9.84,-59.06 ; 9.84,-59.06 14.76,-63.98 34.45,-63.98 39.37,-59.06 ; 59.06,-59.06 63.98,-63.98 83.66,-63.98 88.58,-59.06 ; 108.27,-59.06 113.19,-63.98 132.87,-63.98 137.8,-59.06 ; 157.48,-59.06 162.4,-63.98 182.09,-63.98 187.01,-59.06 ; 206.69,-59.06 211.61,-63.98 231.3,-63.98 236.22,-59.06 ; 255.91,-59.06 260.83,-63.98 280.51,-63.98 285.43,-59.06 ; 305.12,-59.06 310.04,-63.98 329.72,-63.98

## 53048-14 [mil]
pads (14):
  oval 27.5x55 hole 19.69: 1(319.88,-49.21) 2(270.67,-49.21) 3(221.46,-49.21) 4(172.24,-49.21) 5(123.03,-49.21) 6(73.82,-49.21) 7(24.61,-49.21) 8(-24.61,-49.21) 9(-73.82,-49.21) 10(-123.03,-49.21) 11(-172.24,-49.21) 12(-221.46,-49.21) 13(-270.67,-49.21) 14(-319.88,-49.21)
Top Overlay:
  rectangle: -329.72,24.61 -310.04,59.06
  rectangle: -280.51,24.61 -260.83,59.06
  rectangle: -231.3,24.61 -211.61,59.06
  rectangle: -182.09,24.61 -162.4,59.06
  rectangle: -132.87,24.61 -113.19,59.06
  rectangle: -83.66,24.61 -63.98,59.06
  rectangle: -34.45,24.61 -14.76,59.06
  rectangle: 14.76,24.61 34.45,59.06
  rectangle: 63.98,24.61 83.66,59.06
  rectangle: 113.19,24.61 132.87,59.06
  rectangle: 162.4,24.61 182.09,59.06
  rectangle: 211.61,24.61 231.3,59.06
  rectangle: 260.83,24.61 280.51,59.06
  rectangle: 310.04,24.61 329.72,59.06
  lines w2: -374.02,59.06 -354.33,59.06 ; -369.09,123.03 -354.33,108.27 ; 369.09,123.03 354.33,108.27 ; 374.02,59.06 354.33,59.06 ; -354.33,59.06 -344.49,59.06 -344.49,24.61 344.49,24.61 344.49,59.06 354.33,59.06 ; -354.33,59.06 -354.33,108.27 ; -354.33,108.27 354.33,108.27 ; 354.33,59.06 354.33,108.27
  lines w8: -374.02,-39.37 -354.33,-39.37 -354.33,-88.58 -375,-88.58 -375,123.03 -369.09,123.03 369.09,123.03 375,123.03 375,-88.58 354.33,-88.58 354.33,-39.37 374.02,-39.37 ; -324.8,59.06 -319.88,78.74 -314.96,59.06 ; -275.59,59.06 -270.67,78.74 -265.75,59.06 ; -226.38,59.06 -221.46,78.74 -216.54,59.06 ; -177.17,59.06 -172.24,78.74 -167.32,59.06 ; -127.95,59.06 -123.03,78.74 -118.11,59.06 ; -78.74,59.06 -73.82,78.74 -68.9,59.06 ; -29.53,59.06 -24.61,78.74 -19.69,59.06 ; 19.69,59.06 24.61,78.74 29.53,59.06 ; 68.9,59.06 73.82,78.74 78.74,59.06 ; 118.11,59.06 123.03,78.74 127.95,59.06 ; 167.32,59.06 172.24,78.74 177.17,59.06 ; 216.54,59.06 221.46,78.74 226.38,59.06 ; 265.75,59.06 270.67,78.74 275.59,59.06 ; 314.96,59.06 319.88,78.74 324.8,59.06
Mechanical 16:
  rectangle: -329.72,-59.06 -310.04,-39.37
  rectangle: -280.51,-59.06 -260.83,-39.37
  rectangle: -231.3,-59.06 -211.61,-39.37
  rectangle: -182.09,-59.06 -162.4,-39.37
  rectangle: -132.87,-59.06 -113.19,-39.37
  rectangle: -83.66,-59.06 -63.98,-39.37
  rectangle: -34.45,-59.06 -14.76,-39.37
  rectangle: 14.76,-59.06 34.45,-39.37
  rectangle: 63.98,-59.06 83.66,-39.37
  rectangle: 113.19,-59.06 132.87,-39.37
  rectangle: 162.4,-59.06 182.09,-39.37
  rectangle: 211.61,-59.06 231.3,-39.37
  rectangle: 260.83,-59.06 280.51,-39.37
  rectangle: 310.04,-59.06 329.72,-39.37
  lines w8: -354.33,-63.98 -334.65,-63.98 -329.72,-59.06 ; -354.33,-39.37 354.33,-39.37 ; -310.04,-59.06 -305.12,-63.98 -285.43,-63.98 -280.51,-59.06 ; -260.83,-59.06 -255.91,-63.98 -236.22,-63.98 -231.3,-59.06 ; -211.61,-59.06 -206.69,-63.98 -187.01,-63.98 -182.09,-59.06 ; -162.4,-59.06 -157.48,-63.98 -137.8,-63.98 -132.87,-59.06 ; -113.19,-59.06 -108.27,-63.98 -88.58,-63.98 -83.66,-59.06 ; -63.98,-59.06 -59.06,-63.98 -39.37,-63.98 -34.45,-59.06 ; -14.76,-59.06 -9.84,-63.98 9.84,-63.98 14.76,-59.06 ; 34.45,-59.06 39.37,-63.98 59.06,-63.98 63.98,-59.06 ; 83.66,-59.06 88.58,-63.98 108.27,-63.98 113.19,-59.06 ; 132.87,-59.06 137.8,-63.98 157.48,-63.98 162.4,-59.06 ; 182.09,-59.06 187.01,-63.98 206.69,-63.98 211.61,-59.06 ; 231.3,-59.06 236.22,-63.98 255.91,-63.98 260.83,-59.06 ; 280.51,-59.06 285.43,-63.98 305.12,-63.98 310.04,-59.06 ; 329.72,-59.06 334.65,-63.98 354.33,-63.98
